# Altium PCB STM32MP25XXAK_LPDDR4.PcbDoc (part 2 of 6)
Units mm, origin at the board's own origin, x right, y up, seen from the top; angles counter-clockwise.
Board outline 120 x 79.6 mm, 4 copper layers (Top Layer, Signal Layer 1, Signal Layer 2, Bottom Layer), stack 1.614 mm thick; 190 components, 143 nets, 1208 pads, 757 vias.
Unrouted connection lines stored in the file: 3.
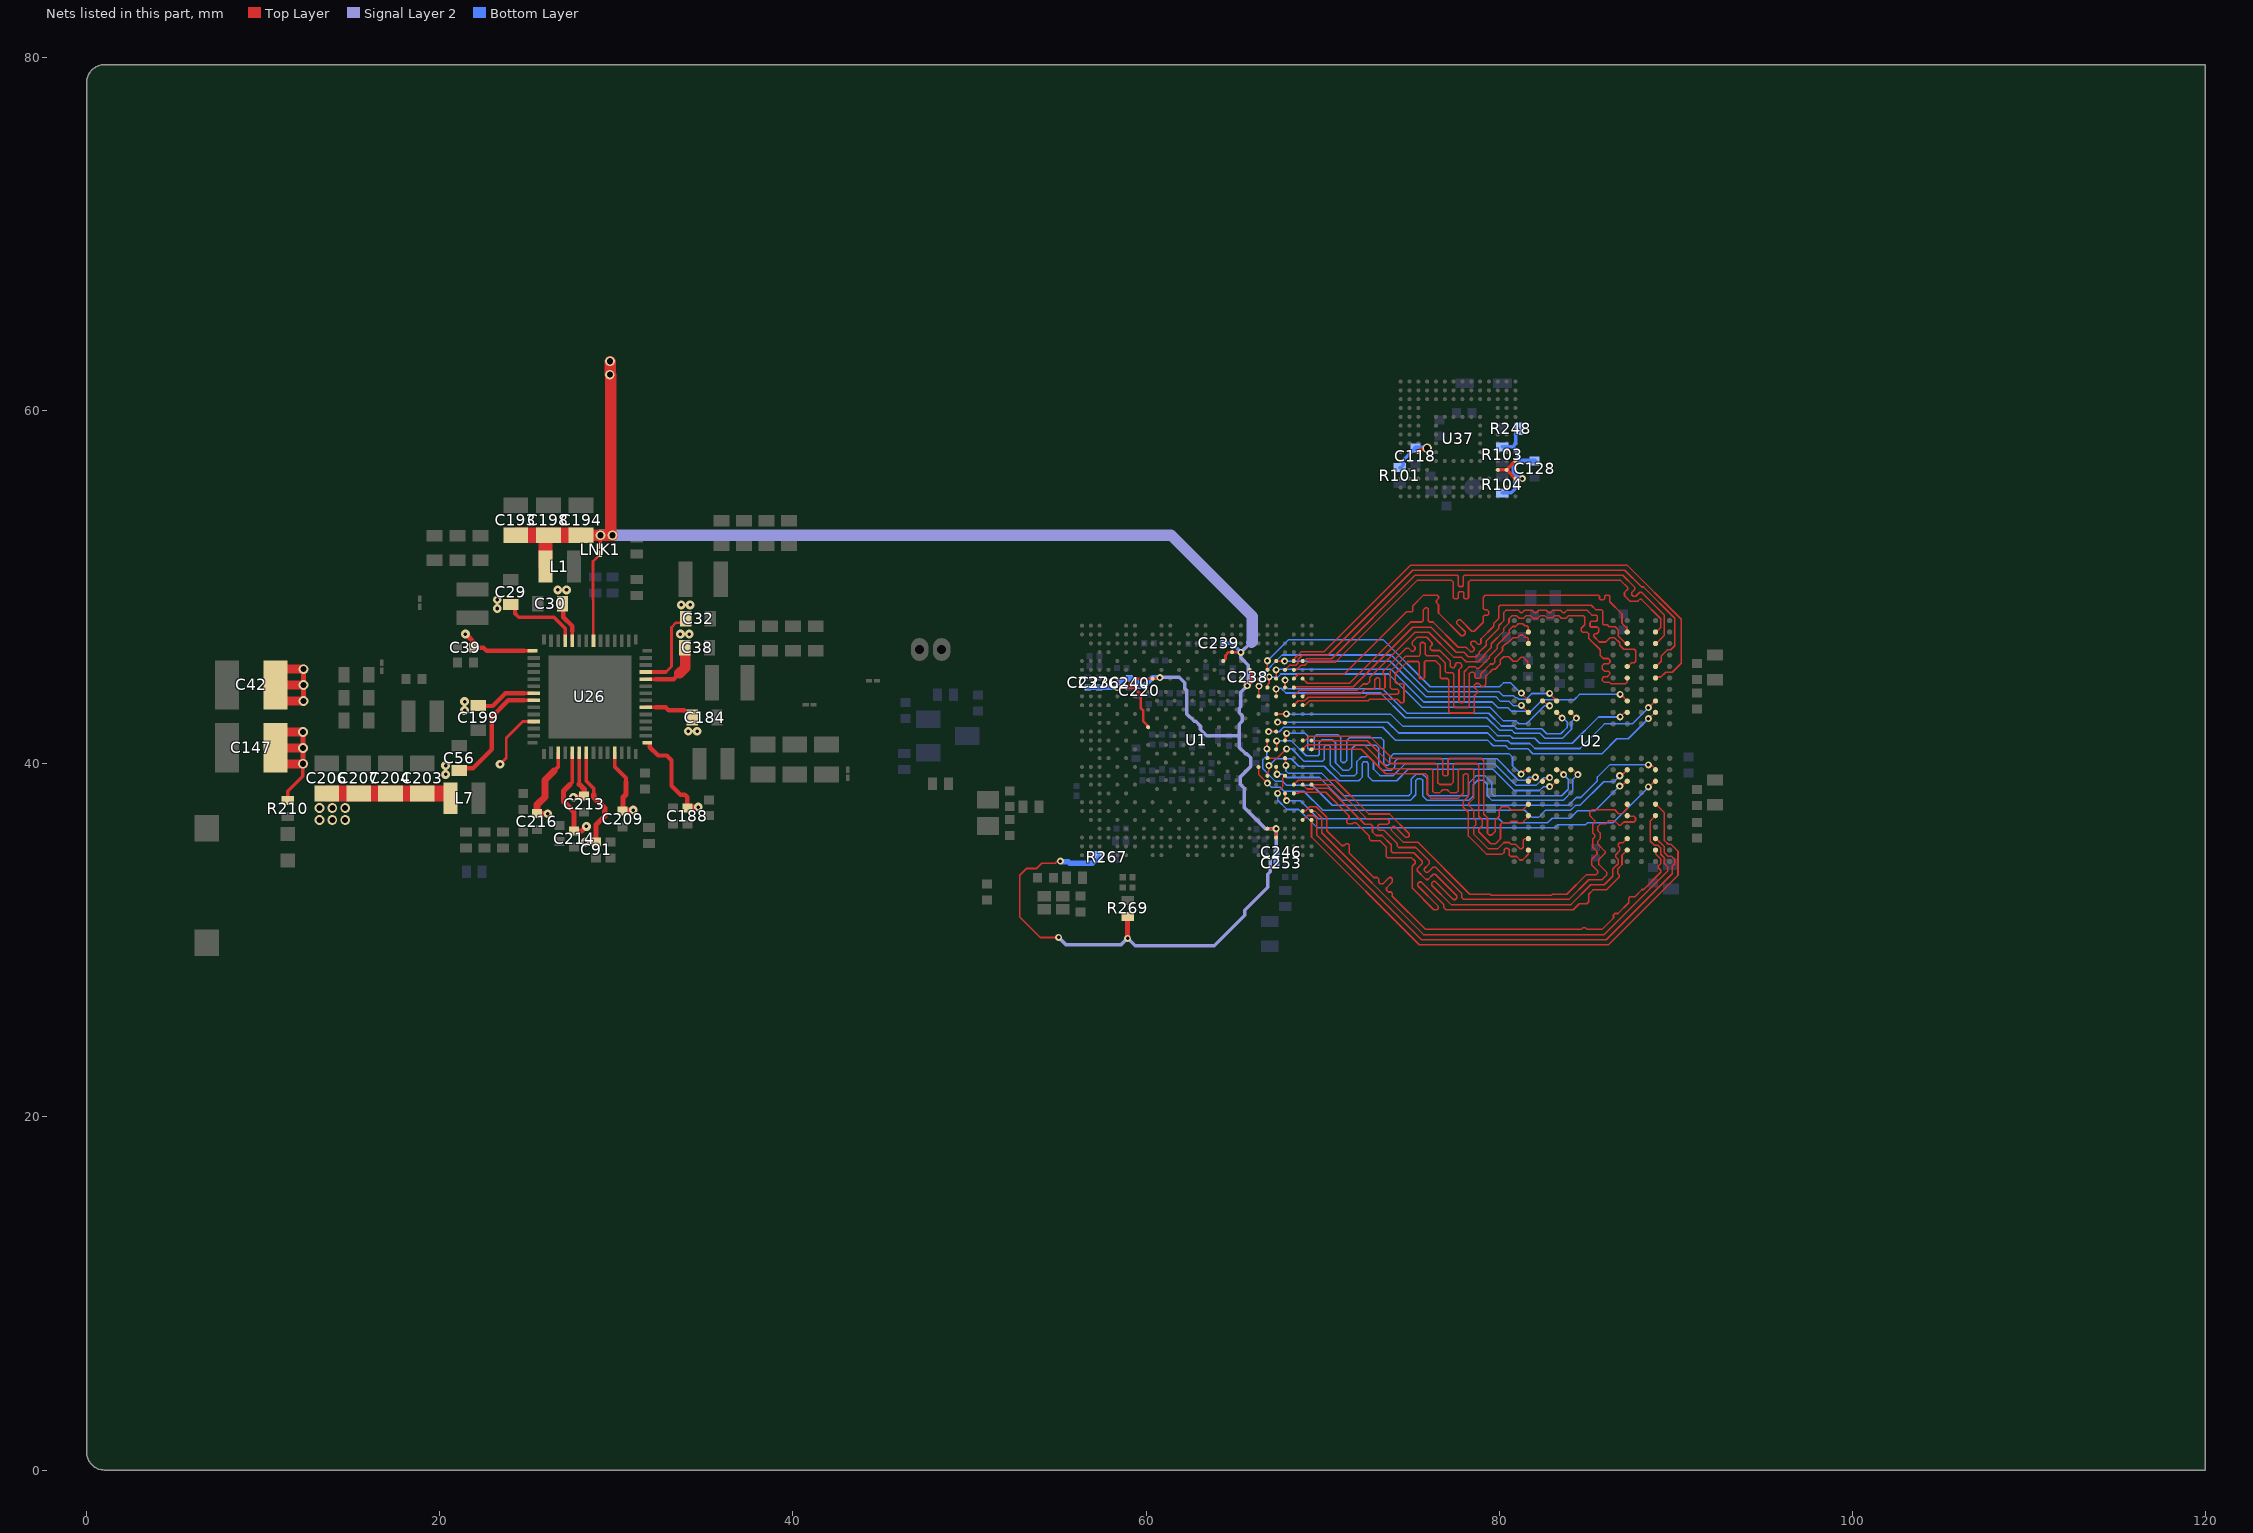
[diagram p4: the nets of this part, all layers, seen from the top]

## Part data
B2: library part MCD-03492, "Switch tactile, SPST-NO, 50mA, 12V, 6x3.8mm", Manufacturer="WURTH ELEKTRONIC", Manufacturer_Part_Number=434121025816, Package=6x3.8mm
C2 C3 C10 C11: library part MCD-01341, "Capacitor, MLCC, 10uF, 6V3, X5R, 20%, 0603, T=0,8mm", Alternate_Manufacturer=MURATA, Alternate_Manufacturer_Part_Number=GRM188R60J106ME84D, Manufacturer_Part_Number=GRM188R60J106ME47D, Package=0603
C4 C5 C6 C7 C8 C12 C13 C14 C15 C16 C17 C18 C19 C20 C21: library part MCD-00006, "Capacitor, MLCC, 100nF, 16V, X7R, +/-10%, 0402, T=0.5mm", Manufacturer=YAGEO, Manufacturer_Part_Number=CC0402KRX7R7BB104, Package=0402
C9 C118 C130: library part MCD-00006, "Capacitor, MLCC, 100nF, 16V, X7R, +/-10%, 0402, T=0.5mm", Alternate_Manufacturer=MURATA, Alternate_Manufacturer_Part_Number=GCM155R71C104KA55D, Manufacturer=YAGEO, Manufacturer_Part_Number=CC0402KRX7R7BB104, Package=0402
C22 C23 C24 C26 C27 C28 C34 C35 C36 C37 C41 C183 C200 C202: library part MCD-00100, "Capacitor, MLCC, 22uF, 6V3, X5R, +/-20%, 0603, T=0,8mm", Alternate_Manufacturer=N/A, Manufacturer=MURATA, Manufacturer_Part_Number=GRM188R60J226MEA0J, Package=0603
C29 C30 C32 C38 C56 C184 C199: library part MCD-00099, "Capacitor, MLCC, 10uF, 10V, X5R, +/-10%, 0603, T=0,8mm", Alternate_Manufacturer=N/A, Manufacturer=MURATA, Manufacturer_Part_Number=GRM188R61A106KE69D, Package=0603
C33: library part MCD-00011, "Capacitor, MLCC, 10nF, 16V, X7R, 10%, 0402, T=0.5mm", Manufacturer=YAGEO, Manufacturer_Part_Number=CC0402KRX7R7BB103, Package=C0402
C39 C43 C188 C213 C216: library part MCD-00095, "Capacitor, MLCC, 1uF, 25V, X5R, +/-10%, 0402, T=0.5mm", Manufacturer=MURATA, Manufacturer_Part_Number=GRM155R61E105KA12, Package=0402
C40: library part MCD-03140, "Capacitor, MLCC, 10uF, 6.3V, X5R, +/-20%, 0402, T=0.5mm", Manufacturer=MURATA, Manufacturer_Part_Number=GRM155R60J106ME05D, Package=0402
C42 C147: library part MCD-01796, "Capacitor, Tantalum, 100uF, 6V3, 40mR, +/-20%,  Type_B (3528 metric), T=1.9mm", Manufacturer=AVX, Manufacturer_Part_Number=TCJB107M006R0040, Package="3528 (metric)"
C44 C45 C46 C47 C48 C49 C50 C51 C52 C53 C54 C55 C57 C58 C59 C60 C62 C63 C64 C65 C66 C67 C68 C69 C70 C71 C72 C73 C74 C75 C76 C77 C82 C83: library part MCD-02377, "Capacitor, MLCC, 1uF, 6.3V, X5R, +/-20%, 0201, T=0,3mm", Manufacturer=MURATA, Manufacturer_Part_Number=GRM033R60J105MEA2, Package=0201
C61 C91 C189 C190 C208 C209 C214 C215 C217: library part MCD-01356, "Capacitor, MLCC, 4.7uF, 6V3, X5R, +/-20%, 0402, T=0.5mm", Manufacturer=MURATA, Manufacturer_Part_Number=GRM155R60J475ME47, Package=0402
C81 C86 C90 C92: library part MCD-00674, "Capacitor, MLCC, 6.8pF, 50V, NPO, +-0.25pF, 0402, T=0.5mm", Alternate_Manufacturer=N/A, Manufacturer=YAGEO, Manufacturer_Part_Number=CC0402CRNPO9BN6R8, Package=0402
C87: library part MCD-00006, "Capacitor,100nF,16V,X7R,10%,0402", Alternate_Manufacturer=MURATA, Alternate_Manufacturer_Part_Number=GCM155R71C104KA55D, Manufacturer=YAGEO, Manufacturer_Part_Number=CC0402KRX7R7BB104, Package=0402
C88: library part MCD-01823, "Capacitor, MLCC, 2.2uF, 6V3, X5R,+/-10%, 0402, T=0.5mm", Alternate_Manufacturer=N/A, Manufacturer=MURATA, Manufacturer_Part_Number=GRM155R60J225KE95D, Package=0402
C117 C128 C148: library part MCD-02606, "Capacitor, MLCC, 2.2uF, 6.3V, X5R, +/-10%, 0402, T=0.5mm", Manufacturer=YAGEO, Manufacturer_Part_Number=CC0402KRX5R5BB225, Package=0402
C151 C250 C252 C260: library part MCD-02377, "Capacitor, MLCC, 1uF, 6.3V, X5R, +/-20%, 0201, T=0,3mm", Alternate_Manufacturer=N/A, Manufacturer=MURATA, Manufacturer_Part_Number=GRM033R60J105MEA2, Package=0201
C185 C186 C187 C193 C194 C198 C203 C204 C206 C207: library part MCD-03139, "Capacitor, MLCC, 22uF, 10V, X5R, +/-20%, 0805, T=1,25mm", Manufacturer=MURATA, Manufacturer_Part_Number=GRM21BR61A226ME51L, Package=0805
C192 C195 C196 C197 C201 C205 C220 C234 C236 C237 C238 C239 C240 C244 C246 C248 C251 C253: library part MCD-01535, "Capacitor, MLCC,100nF, 10V, X7R, +/-10%, 0201, T=0.3mm", Alternate_Manufacturer=N/A, Manufacturer=MURATA, Manufacturer_Part_Number=GRM033R61A104KE15, Package=0201
C219: library part MCD-02198, "Capacitor, MLCC, 10nF, 50V, X7R, +/-10%, 0402, T=0.5mm", Manufacturer=YAGEO, Manufacturer_Part_Number=CC0402KRX7R9BB103, Package=0402
C225: library part MCD-01534, "Capacitor, MLCC, 4,7uF, 6V3, X5R, +/-20%, 0201, T=0.5mm", Alternate_Manufacturer=N/A, Manufacturer=MURATA, Manufacturer_Part_Number=GRM035R60J475ME15, Package=0201
C235: library part MCD-02235, "Capacitor, MLCC, 2.2uF, 10V, X5R,+/-10%, 0201, T=0.5mm", Manufacturer=MURATA, Manufacturer_Part_Number=GRM033R61A225KE47D, Package=0201
CN12: library part MCD-00655, "Header 2 circuits, 1.25mm Pitch ,  Vertical, with Friction Lock", Alternate_Manufacturer=N/A, Manufacturer=MOLEX, Manufacturer_Part_Number=53047-0210
D6: library part MCD-03280, "Diode, Schottky, Dual Common Cathode, 0V3, 300mA, 40V, SOT-23", Manufacturer=STMICROELECTRONICS, Manufacturer_Part_Number=BAT54CFILM, Package=SOT-23
D7: library part MCD-00034, Manufacturer=STMICROELECTRONICS, Manufacturer_HQ_COO=EU
L1 L6: library part MCD-03143, "Inductor, 2.2uH, +/-20%, Itemp= 1700mA, Isat= 2400mA, 0R140, 0806, T=1mm", Manufacturer=MURATA, Manufacturer_Part_Number=DFE201610E-2R2M{}P2, Package=0806
L2 L4: library part MCD-03142, "Inductor, 0.68uH, +/-20%, Itemp= 3900mA, Isat= 5400mA, 0R031, 1008, T=1.2mm", Manufacturer=MURATA, Manufacturer_Part_Number=DFE252012F-R68M{}P2, Package=1008
L3 L5 L7: library part MCD-03141, "Inductor, 0.68uH, +/-20%, Itemp= 3100mA, Isat= 4300mA, 0R043, 0806, T=1mm", Manufacturer=MURATA, Manufacturer_Part_Number=DFE201610E-R68M{}P2, Package=0806
LD11: library part MCD-00588, "LED Green, 0603 SMD, Forward Voltage Typ=2V, Max=2.5V", Alternate_Manufacturer="VISHAY SEMICONDUCTOR OPTO DIVISION", Alternate_Manufacturer_Part_Number=VLMTG1300-GS08, Manufacturer="OSRAM OPTO SEMICONDUCTORS", Manufacturer_Part_Number="LG Q396-PS-35", Package="LED 0603"
LNK1 LNK2 LNK4 LNK7 LNK8 LNK11: library part MCD-02777, "Track link on PCB 200um width for layout routing", Manufacturer=N/A
R1 R2: library part MCD-02253, "Resistor, 240R, 0201, +/-1%, 1/20W", Alternate_Manufacturer=N/A, Manufacturer=YAGEO, Manufacturer_Part_Number=RC0201FR-07240RL, Package=0201
R11: library part MCD-00056, "Resistor, 0R, 0603, +/-5%, 1/10W", Manufacturer=YAGEO, Manufacturer_Part_Number=RC0603JR-070RL, Package=0603
R27 R272: library part MCD-00053, "Resistor,10K,0402,1%,1/16W", Alternate_Manufacturer=N/A, Manufacturer=YAGEO, Manufacturer_Part_Number=RC0402FR-0710KL, Package=0402
R42: library part MCD-00053, "Resistor, 10K, 0402, +/-1%, 1/16W", Alternate_Manufacturer=N/A, Manufacturer=YAGEO, Manufacturer_Part_Number=RC0402FR-0710KL, Package=0402
R46 R57 R59 R60 R61 R64 R75 R81 R267 R269 R286: library part MCD-00052, "Resistor,0R,0402,5%,1/16W", Alternate_Manufacturer=N/A, Manufacturer=YAGEO, Manufacturer_Part_Number=RC0402JR-070RL, Package=0402
R66: library part MCD-00058, "Resistor, 20R, 0402, +/-1%, 1/16W", Alternate_Manufacturer=N/A, Manufacturer=YAGEO, Manufacturer_Part_Number=RC0402FR-0720RL, Package=0402
R67: library part MCD-00052, "Resistor, 0R, 0402, +/-5%, 1/16W", Manufacturer=YAGEO, Manufacturer_Part_Number=RC0402JR-070RL, Package=0402
R101 R103 R104 R248: library part MCD-00053, "Resistor,10K,0402,1%,1/16W", Manufacturer=YAGEO, Manufacturer_Part_Number=RC0402FR-0710KL, Package=0402
R210: library part MCD-00441, "Resistor,270R,0402,1%,1/16W", Manufacturer=YAGEO, Manufacturer_Part_Number=RC0402FR-07270RL, Package=0402
R260 R261: library part MCD-00068, "Resistor,1K5,0402,1%,1/16W", Manufacturer=YAGEO, Manufacturer_Part_Number=RC0402FR-071K5L, Package=0402
TP21: library part MCD-00074, "Test Point 1mm", Manufacturer=n/a
U1: library part MCD-03375, "MPU , 2xCortex-A35@1.5GHz, Cortex-M33@400MHz, TFBGA 14x14, pitch 0.5, 808 KB SRAM, With Crypto", Manufacturer=STMICROELECTRONICS, Package=TFBGA
U2: library part MCD-04160, "Memory, LPDDR4 SDRAM,1V8, 32Gbit, 2133MHz", Manufacturer=MICRON, Package=TFBGA-200
U26: library part MCD-03000, "STPMIC2", Manufacturer=STMICROELECTRONICS, Package=VQFN
U37: library part MCD-02799, "Memory, eMMC, 4GB, 15nm ,WFBGA , 153 pins", Manufacturer=KIOXIA, Manufacturer_Part_Number=THGBMTG5D1LBAIL, Package=WFBGA153
X1: library part MCD-01479, "Crystal, 32.768kHz, 6pF, +/-20ppm, 80K, 2.05x1.2mm", Manufacturer=NDK, Manufacturer_Part_Number=NX2012SA-32.768KHZ-EXS00A-MU00527, Package=2.05x1.2mm
X2: library part MCD-02344, "Crystal, 40MHz, 6pF, +/-20ppm, 80R, 1.6x1.2mm", Manufacturer=NDK, Manufacturer_Part_Number=NX1612SA-40MHZ-EXS00A-CS13836, Package=1.6x1.2mm

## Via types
v1: diameter 0.55, hole 0.35, Top Layer to Bottom Layer, 277 vias
v2: diameter 0.4, hole 0.2, Top Layer to Bottom Layer, tented both sides, 229 vias
v3: diameter 0.5, hole 0.2, Top Layer to Bottom Layer, 146 vias
v4: diameter 0.4, hole 0.2, Top Layer to Bottom Layer, 105 vias

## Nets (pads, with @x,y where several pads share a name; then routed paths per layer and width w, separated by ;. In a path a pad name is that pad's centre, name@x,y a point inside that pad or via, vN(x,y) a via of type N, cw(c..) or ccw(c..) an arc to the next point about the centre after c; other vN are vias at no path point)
1V8: C118.2 C128.2 C193.2 C194.2 C198.2 C220.2 C236.2 C237.2 C238.2 C239.2 C240.2 C246.2 C253.2 L1.2 LNK1.2 R101.2 R103.2 R104.2 R248.2 R267.2 R269.1 U1.1E1 U1.AD22 U1.AE23 U1.D18 U1.E17 U1.F20 U1.G5 U1.G7 U1.G9 U1.G19 U1.H6 U37.C6 U37.M4 U37.N4 U37.P3 U37.P5 | length 137.4
  Top Layer w0.1: v2(55.049,30.165) 54.012,30.165 52.854,31.323 52.854,33.688 53.244,34.078 53.813,34.078 54.103,34.368 54.86,34.368 54.967,34.474 55.127,34.474 v2(55.146,34.494)
  Top Layer w0.15: U1.G5@58.375,44.825 v2(58.375,44.325) U1.H6@58.875,44.325 ; U1.1E1@60.125,42.075 60.125,42.097 60.085,42.137 60.085,42.17 59.835,42.42 59.835,43.035 59.702,43.168 59.702,43.926 59.304,44.325 U1.H6@58.875,44.325 ; v2@60.792,44.887 v2(60.79,44.885) 60.73,44.825 U1.G9@60.375,44.825 U1.G7@59.375,44.825 U1.H6@58.875,44.325 ; U1.E17@64.375,45.825 64.375,45.828 64.5,45.953 64.5,46.139 64.683,46.322 U1.D18@64.872,46.322 ; U1.D18@64.853,46.325 U1.D18@64.875,46.325 65.372,46.325 v2(65.378,46.319) ; U1.G19@65.378,44.822 65.735,44.465 v2(65.735,44.426) 65.735,44.412 65.973,44.651 65.973,45.205 65.875,45.303 U1.F20@65.875,45.325 ; U1.AD22@66.875,36.325 v2(67.375,36.325) U1.AE23@67.375,35.825 ; U37.P3@80.925,56.155 v2(81.325,56.155)
  Top Layer w0.2: LNK1.2@29.1,52.348 v1(29.1,52.95) ; U37.C6@75.425,57.655 75.602,57.832 75.877,57.832 v1(75.925,57.88) ; U37.M4@79.925,56.655 U37.N4@80.425,56.655 ; U37.P3@80.925,56.155 U37.N4@80.425,56.655 ; U37.P5@80.925,57.155 U37.N4@80.425,56.655
  Top Layer w0.3: R269.1@58.956,31.358 58.956,30.117 v2(58.962,30.112)
  Top Layer w0.64: C194.2@28,52.95 v1(29.1,52.95) v1(29.78,52.95) 29.674,53.056 v1@29.674,62.004 ; v1@29.66,62.075 v1@29.66,62.782
  Top Layer w0.8: L1.2@25.995,51.175 25.995,52.9 26.045,52.95 C198.2@26.15,52.95
  Top Layer w0.9: C193.2@24.3,52.95 C198.2@26.045,52.95 ; C198.2@26.15,52.95 C194.2@28,52.95
  Signal Layer 2 w0.2: v2(55.049,30.165) 55.449,29.766 58.598,29.766 v2@58.944,30.112 ; v2(58.962,30.112) 59.386,29.688 63.861,29.688 65.603,31.43 65.603,31.711 66.9,33.008 66.9,33.754 67.041,33.895 67.041,34.559 67.375,34.893 v2(67.375,36.325) ; v2(60.79,44.885) 60.811,44.906 61.89,44.906 62.2,44.596 62.2,44.264 62.32,44.144 62.32,42.814 62.725,42.409 62.81,42.409 63.077,42.143 ; 63.075,42.156 63.077,42.155 63.077,42.143 ; 65.285,41.575 65.285,40.928 65.64,40.572 65.694,40.572 65.93,40.336 65.93,39.851 65.349,39.271 65.349,38.835 65.569,38.615 65.569,37.527 65.566,37.525 66.77,36.322 v2@67.372,36.322 ; v2@65.674,44.353 65.773,44.452 65.773,44.591 65.794,44.612 65.794,45.583 65.378,45.999 v2(65.378,46.319) 65.927,46.868 65.981,46.868 ; v2@65.734,44.411 65.375,44.053 65.375,43.231 65.284,43.14 65.284,42.894 65.44,42.738 65.44,42.406 65.285,42.251 65.285,41.593 63.445,41.593 63.077,41.961 63.077,42.143
  Signal Layer 2 w0.64: v1@29.1,52.955 v1@29.78,52.955 ; v1(29.78,52.95) 61.405,52.95 ; 61.411,52.956 66.023,48.344 66.023,46.91 65.981,46.868
  Bottom Layer w0.15: v2(67.375,36.325) 67.375,34.827 67.391,34.811
  Bottom Layer w0.2: C239.2@64.4,46.837 64.86,46.837 v2(65.378,46.319) ; v2@65.735,44.411 65.958,44.635 65.958,44.819 C238.2@66.033,44.894 ; R101.2@74.375,56.775 74.425,56.775 74.58,56.93 74.58,57.2 75.08,57.7 75.08,57.725 75.235,57.88 C118.2@75.26,57.88 ; R103.2@80.171,57.961 80.769,57.961 ; R104.2@80.175,55.355 80.69,55.355 80.885,55.55 80.885,55.998 81.061,56.174 ; 81.075,57.136 81.075,57.655 80.769,57.961 ; R248.2@81.107,58.98 80.952,58.825 80.952,58.144 80.769,57.961
  Bottom Layer w0.25: C253.2@67.391,34.385 67.391,34.811 C246.2@67.391,34.986
  Bottom Layer w0.3: v2(55.146,34.494) 55.165,34.474 55.236,34.474 55.259,34.452 55.612,34.452 55.689,34.375 56.975,34.375 57.123,34.523 57.218,34.523 57.323,34.628 R267.2@57.323,34.723 ; C237.2@56.696,44.325 C236.2@57.35,44.325 v2@58.386,44.325 ; v2(58.375,44.325) 58.394,44.344 58.394,44.53 58.689,44.825 59.025,44.825 C240.2@59.025,44.85 ; C240.2@58.984,44.85 59.125,44.85 59.15,44.825 59.19,44.825 59.3,44.715 59.399,44.715 59.54,44.574 59.54,44.475 C220.2@59.609,44.406 59.634,44.431 59.911,44.431 60.372,44.892 60.783,44.892 v2(60.79,44.885) ; C118.2@75.26,57.88 v1(75.925,57.88) ; v2(81.325,56.155) 81.306,56.174 81.061,56.174 80.867,56.368 80.867,56.928 81.075,57.136 81.306,57.136 81.325,57.155 C128.2@82.015,57.155
  other v1: 29.631,62.047 29.642,62.8
1V8_FB: LNK1.1 U26.35 | length 5.1
  Top Layer w0.15: U26.35@28.7,46.97 28.7,49.311 28.675,49.336 28.675,51.473 LNK1.1@29.1,51.898
3V3: C203.2 C204.2 C206.2 C207.2 C216.2 L7.2 U26.3 U26.53 | length 15.3
  Top Layer w0.15: v3(23.41,39.977) 23.762,40.329 23.762,41.465 24.697,42.4 U26.53@25.33,42.4 ; U26.53@25.12,42.369 25.419,42.369 U26.53@25.45,42.4
  Top Layer w0.21: 26.473,39.598 26.7,39.825 U26.3@26.7,40.63
  Top Layer w0.3: C216.2@25.475,37.175 C216.2@25.5,37.175 v3@26.085,37.175
  Top Layer w0.4: C216.2@25.5,37.175 25.514,37.189 25.514,37.685 25.96,38.131 25.96,39.085 26.473,39.598
  Top Layer w0.9: C206.2@13.587,38.323 C203.2@19,38.323 20.362,38.323 L7.2@20.387,38.298
  other v1: 13.187,36.823 13.912,36.823 14.637,36.823 13.187,37.498 13.912,37.498 14.637,37.498
  other v3: 26.11,37.175
5V_HDMI: C91.1 U26.7 | length 6.1
  Top Layer w0.21: U26.7@28.3,40.63 28.3,39.025 28.715,38.61 28.715,38.253
  Top Layer w0.3: v3(28.24,35.58) C91.1@28.85,35.58 ; 28.715,38.253 28.715,38.118 29.335,37.498 29.335,37.035 28.85,36.55 C91.1@28.85,35.73
5V_STLK: C29.2 C30.2 C32.2 C38.2 C39.2 C42.1 C56.2 C147.1 C184.2 C188.2 C199.2 C209.2 C213.2 R210.1 U26.6 U26.11 U26.15 U26.20 U26.24 U26.25 U26.38 U26.39 U26.43 U26.49 U26.50 | length 61
  Top Layer w0.15: 32.8,45.2 33.125,45.525 33.125,47.731 33.388,47.994 33.819,47.994 C32.2@33.925,48.1
  Top Layer w0.2: R210.1@11.386,37.915 11.386,38.449 12.244,39.307 v1@12.244,39.994
  Top Layer w0.21: C29.2@24.025,49.05 24.262,48.813 24.262,48.513 24.475,48.3 26.464,48.3 27.1,47.664 U26.39@27.1,46.97 ; 24.775,43.6 U26.50@25.33,43.6 ; 24.775,44 U26.49@25.33,44 ; 24.775,46.4 U26.43@25.33,46.4 ; U26.38@27.5,46.97 27.5,47.525 ; 27.9,38.85 U26.6@27.9,40.63 ; U26.11@29.9,40.63 29.9,39.843 30.54,39.203 30.54,38.975 ; U26.15@31.67,41.2 U26.15@31.745,41.2 U26.15@31.785,41.2 ; U26.20@31.67,43.2 32.225,43.2 ; U26.24@31.67,44.8 32.207,44.8 ; U26.25@31.67,45.2 32.8,45.2
  Top Layer w0.25: C56.2@21.1,39.75 21.875,39.75 22.95,40.825 22.95,42.669 23.881,43.6 24.775,43.6 ; 21.695,47.125 21.699,47.125 21.845,46.979 21.845,46.685 C39.2@21.955,46.575 ; C39.2@22.005,46.575 22.475,46.575 22.65,46.4 24.775,46.4 ; C199.2@22.175,43.275 22.991,43.275 23.716,44 24.775,44 ; C30.2@26.925,49.075 26.994,49.006 26.994,48.308 27.5,47.802 27.5,47.525 ; 31.895,41.095 31.895,40.947 32.371,40.472 32.853,40.472 33.125,40.2 33.125,38.759 33.634,38.25 33.879,38.25 34.025,38.104 C188.2@34.025,37.55 ; 32.207,44.8 33.25,44.8 33.575,45.125 ; 32.225,43.2 32.788,43.2 32.963,43.025 33.847,43.025 33.972,42.9 34.05,42.9 34.247,42.703 C184.2@34.247,42.625
  Top Layer w0.3: v1@12.25,40 12.25,40.902 12.25,40.906 v1@12.25,41.8 ; v1@12.275,43.563 12.275,44.463 v1@12.275,45.363 ; v3@21.444,47.376 21.695,47.125 ; v3(27.565,38.11) 28.175,38.11 28.174,38.111 28.174,38.576 27.9,38.85 ; C209.2@30.35,37.38 C209.2@30.375,37.38 ; 30.54,38.975 30.54,38.269 30.375,38.104 C209.2@30.375,37.38 ; v3(30.96,37.38) C209.2@30.375,37.38 ; C188.2@34.025,37.55 v3(34.635,37.55)
  Top Layer w0.5: C147.1@10.686,39.994 12.244,39.994 v1@12.269,39.994 ; C147.1@10.686,40.906 12.25,40.906 v1@12.269,40.906 ; C147.1@10.686,41.806 v1@12.269,41.806 ; C42.1@10.686,43.557 v1@12.269,43.557 ; C42.1@10.686,44.468 v1@12.269,44.468 ; C42.1@10.686,45.368 v1@12.269,45.368
  Top Layer w0.6: 33.575,45.125 33.9,45.45 C38.2@33.9,46.175
  other v1: 12.251,40.002 12.251,40.902 12.251,41.802 12.276,43.565 12.276,44.465 12.276,45.365
  other v3: 20.325,39.4 20.325,39.9 34.075,41.85 34.575,41.85 21.4,43.025 21.4,43.525 21.45,47.348 33.625,47.35 34.125,47.35 23.25,48.8 33.675,49 34.175,49 23.25,49.3 26.675,49.85 27.175,49.85
5V_VCONN: C214.1 U26.5 | length 5.7
  Top Layer w0.21: 27.378,38.827 27.5,38.95 U26.5@27.5,40.63
  Top Layer w0.3: 27.378,38.827 27.01,38.46 27.01,37.865 27.6,37.275 C214.1@27.6,36.2 28.04,36.2 v3(28.3,36.46)
DDR_CA0_A: U1.V24 U2.H2 | length 24.6
  Top Layer w0.09: v2@67.471,38.421 67.471,38.432 67.735,38.695 67.735,39.185 U1.V24@67.875,39.325 ; v4(88.46,38.69) 88.497,38.69 88.814,39.007 U2.H2@88.873,39.007
  Bottom Layer w0.09: v2@67.463,38.318 67.463,37.935 67.983,37.415 68.659,37.415 69.683,36.39 83.176,36.39 83.326,36.54 84.88,36.54 85.007,36.667 86.447,36.667 v4@88.461,38.681
  other v2: 67.46,38.325
DDR_CA0_B: U1.M24 U2.R2 | length 23.5
  Top Layer w0.09: v2@67.46,42.35 67.484,42.326 U1.M24@67.875,42.325 ; v4@88.472,43.19 88.826,43.544 U2.R2@88.859,43.544
  Bottom Layer w0.09: v2(67.46,42.365) 73.699,42.365 ; 73.7,42.36 74.314,41.746 79.358,41.746 79.791,41.313 80.496,41.313 80.654,41.155 81.746,41.155 82.031,40.87 84.581,40.87 85.973,42.262 87.538,42.262 v4@88.461,43.185
  other v4: 88.46,43.19
DDR_CA1_A: U1.P22 U2.J2 | length 25.9
  Top Layer w0.09: v2@66.875,40.9 U1.P22@66.875,41.325 ; v4(88.46,39.94) 88.518,39.881 88.689,39.881 88.86,39.71 U2.J2@88.86,39.665
  Bottom Layer w0.09: v2@66.851,40.845 66.851,40.48 66.622,40.251 66.622,40.045 66.62,40.043 66.62,39.757 66.622,39.755 66.622,39.721 67.339,39.005 67.74,39.005 67.954,38.791 69.421,38.791 70.552,37.66 83.935,37.66 84.371,38.096 84.618,38.096 85.572,39.05 85.572,39.255 86.257,39.94 v4(88.46,39.94)
  other v2: 66.85,40.85
DDR_CA1_B: U1.N23 U2.P2 | length 24
  Top Layer w0.09: v2@66.946,41.838 67.362,41.838 U1.N23@67.375,41.825 ; v4(88.46,42.565) 88.483,42.565 88.833,42.915 U2.P2@88.86,42.915
  Bottom Layer w0.09: v2(66.95,41.825) 67.542,41.825 67.792,42.075 73.404,42.075 74.153,41.326 79.367,41.326 79.669,41.023 80.374,41.023 80.533,40.865 81.624,40.865 81.909,40.58 85.826,40.58 86.671,41.425 87.315,41.425 88.45,42.56 v4@88.461,42.56
DDR_CA2_A: U1.V22 U2.H9 | length 20.3
  Top Layer w0.09: U1.V22@66.877,39.334 66.877,39.497 66.947,39.567 66.947,39.847 v2@66.95,39.85 ; v4@82.859,38.719 82.913,38.774 83.019,38.774 U2.H9@83.26,39.015
  Bottom Layer w0.09: v2@66.966,39.895 67.358,40.287 68.23,40.287 68.647,39.869 70.104,39.869 70.926,39.046 72.053,39.046 72.239,39.232 72.239,40.017 72.339,40.117 72.501,40.117 72.595,40.024 72.595,39.281 72.83,39.046 74.2,39.046 74.859,39.705 79.637,39.705 80.852,38.49 82.293,38.49 82.511,38.708 v4@82.86,38.708
  other v2: 66.965,39.9
  other v4: 82.86,38.715
DDR_CA2_B: U1.J21 U2.R9 | length 19.8
  Top Layer w0.09: U1.J21@66.375,43.825 66.387,43.837 v2@66.387,44.388 ; v4(82.86,43.99) 82.86,43.977 83.26,43.577 U2.R9@83.26,43.565
  Bottom Layer w0.09: v2(66.4,44.4) 66.4,44.478 66.494,44.572 66.494,44.951 67.71,46.166 73.892,46.166 75.974,44.084 79.99,44.084 80.217,43.857 80.817,43.857 80.918,43.756 81.021,43.756 81.117,43.66 81.519,43.66 81.846,43.987 v4@82.858,43.987
DDR_CA3_A: U1.T22 U2.H10 | length 21.6
  Top Layer w0.09: U1.T22@66.875,40.325 67.433,40.325 v2(67.961,40.853) ; U2.H10@82.467,39.008 82.625,39.166 82.801,39.166 v4(82.86,39.225)
  Bottom Layer w0.09: v2@67.964,40.849 68.253,40.849 68.943,40.159 70.015,40.159 70.104,40.248 70.104,40.975 70.195,41.066 70.356,41.066 70.443,40.978 70.443,39.939 71.046,39.336 71.816,39.336 71.949,39.469 71.949,40.137 72.219,40.407 72.621,40.407 72.885,40.144 72.885,39.706 73.255,39.336 74.013,39.336 74.671,39.995 79.757,39.995 80.972,38.78 82.094,38.78 82.534,39.22 v4@82.861,39.22
DDR_CA3_B: U1.H22 U2.R10 | length 18.7
  Top Layer w0.09: U1.H22@66.875,44.325 66.9,44.35 66.9,44.496 66.975,44.571 66.975,44.918 v2(66.971,44.921) ; U2.R10@82.46,43.565 82.514,43.565 82.789,43.29 v4(82.86,43.29)
  Bottom Layer w0.09: v2@66.972,44.916 67.471,44.916 67.646,45.091 73.736,45.091 75.628,43.2 79.488,43.2 80.255,42.433 80.96,42.433 81.118,42.275 81.559,42.275 82.569,43.285 v4@82.861,43.285
DDR_CA4_A: U1.R23 U2.H11 | length 21.6
  Top Layer w0.09: U1.R23@67.375,40.825 67.4,40.85 v2(67.4,41.3) ; U2.H11@81.66,39.015 81.714,39.015 81.882,39.183 82.003,39.183 v4(82.06,39.24)
  Bottom Layer w0.09: v2(67.4,41.3) 68.236,41.3 69.072,40.465 69.736,40.465 69.814,40.543 69.814,41.209 69.962,41.356 70.569,41.356 70.733,41.192 70.733,40.059 71.166,39.626 71.466,39.626 71.659,39.819 71.659,40.858 71.849,41.048 73.031,41.048 73.175,40.904 73.175,39.826 73.375,39.626 73.892,39.626 74.093,39.826 74.093,40.136 74.241,40.285 79.877,40.285 81.092,39.07 81.517,39.07 81.686,39.239 v4@82.057,39.239
DDR_CA4_B: U1.F22 U2.R11 | length 17.4
  Top Layer w0.09: U1.F22@66.875,45.325 v2(66.875,45.841) ; v4@81.26,43.99 81.66,43.59 U2.R11@81.66,43.565
  Bottom Layer w0.09: v2@66.876,45.836 68.06,47.02 73.448,47.02 76.094,44.374 80.027,44.374 ; 80.044,44.379 80.249,44.584 80.665,44.584 v4@81.259,43.99
  other v4: 81.26,44.005
DDR_CA5_A: U1.P24 U2.J11 | length 21.1
  Top Layer w0.09: U1.P24@67.875,41.325 67.902,41.352 67.902,41.702 v2@67.95,41.75 ; v4@81.235,39.415 81.461,39.641 81.636,39.641 U2.J11@81.66,39.665
  Bottom Layer w0.09: v2@67.971,41.725 69.016,41.725 69.155,41.586 69.155,40.888 69.257,40.786 69.444,40.786 69.524,40.867 69.524,41.508 69.662,41.646 70.873,41.646 71.023,41.496 71.023,40.18 71.125,40.078 71.257,40.078 71.369,40.19 71.369,41.327 71.513,41.471 73.311,41.471 73.465,41.317 73.465,40.008 73.556,39.916 73.712,39.916 73.803,40.007 73.803,40.351 74.032,40.58 80.558,40.58 80.76,40.378 80.76,40.364 80.761,40.363 80.761,39.9 v4@81.251,39.41
  other v2: 67.97,41.73
  other v4: 81.25,39.415
DDR_CA5_B: U1.E23 U2.P11 | length 15.5
  Top Layer w0.09: U1.E23@67.375,45.825 67.377,45.823 67.852,45.823 v2(67.855,45.82) ; v4@81.268,43.3 81.652,42.915 U2.P11@81.66,42.915
  Bottom Layer w0.09: v2@67.856,45.815 73.833,45.815 75.854,43.794 79.829,43.794 80.085,43.538 80.573,43.538 80.822,43.289 81.24,43.289 v4@81.261,43.31
  other v4: 81.26,43.315
DDR_CKE0_A: U1.U21 U2.J4 | length 23.3
  Top Layer w0.09: U1.U21@66.376,39.833 66.376,39.409 v2(66.875,38.91) ; v4@86.979,39.384 U2.J4@87.26,39.665
  Bottom Layer w0.09: v2@66.876,38.905 67.111,38.67 67.603,38.67 67.818,38.455 68.939,38.455 70.024,37.37 81.458,37.37 81.863,36.965 82.229,36.965 82.629,37.365 84.05,37.365 84.329,37.644 84.576,37.644 85.922,38.99 86.515,38.99 v4@86.836,39.311
  other v4: 86.835,39.325
DDR_CKE0_B: U1.L23 U2.P4 | length 21.3
  Top Layer w0.09: U1.L23@67.375,42.825 67.816,42.826 67.88,42.889 v2@67.965,42.889 ; v4(86.86,42.665) 87.079,42.884 87.229,42.884 U2.P4@87.26,42.915
  Bottom Layer w0.09: v2@67.951,42.82 73.855,42.82 74.555,42.12 79.395,42.12 79.911,41.603 80.616,41.603 80.774,41.445 82.02,41.445 82.305,41.16 84.141,41.16 85.634,42.654 v4@86.855,42.654
  other v2: 67.95,42.825
DDR_CLK_A_N: U1.T24 U2.J9 | length 22.6
  Top Layer w0.09: U1.T24@67.876,40.333 67.901,40.308 67.901,39.933 v2@67.926,39.908 ; U2.J9@83.26,39.665 83.3,39.625 83.428,39.625 v4@83.659,39.394
  Bottom Layer w0.09: v2@67.929,39.902 67.929,39.595 68.048,39.476 69.936,39.476 71.211,38.2 74.886,38.2 75.034,38.348 75.034,39.159 75.29,39.415 75.683,39.415 75.925,39.172 75.925,38.286 76.011,38.2 78.213,38.2 78.291,38.277 78.291,38.915 78.692,39.316 79.204,39.316 79.578,38.941 79.578,38.301 79.68,38.2 83.553,38.2 83.915,38.561 83.915,39.135 v4(83.66,39.39)
  other v2: 67.925,39.91
DDR_CLK_A_P: U1.U23 U2.J8 | length 23.2
  Top Layer w0.09: U1.U23@67.375,39.825 67.375,39.46 v2(67.425,39.41) ; U2.J8@84.06,39.665 84.1,39.625 84.217,39.625 84.448,39.394 v4@84.459,39.394
  Bottom Layer w0.09: v2@67.427,39.404 67.766,39.404 67.945,39.226 69.832,39.226 71.108,37.95 74.989,37.95 75.284,38.245 75.284,39.055 75.393,39.165 75.579,39.165 75.675,39.069 75.675,38.182 75.908,37.95 78.317,37.95 78.541,38.174 78.541,38.811 78.795,39.066 79.1,39.066 79.328,38.838 79.328,38.198 79.576,37.95 83.657,37.95 84.165,38.458 84.165,39.096 v4(84.46,39.39)
DDR_CLK_B_N: U1.H24 U2.P9 | length 19.1
  Top Layer w0.09: U1.H24@67.875,44.325 v2(67.875,44.74) ; U2.P9@83.26,42.915 83.574,42.601 v4(83.574,42.59)
  Bottom Layer w0.09: v2(67.875,44.74) 67.851,44.716 67.851,44.441 68.027,44.265 73.389,44.265 74.785,42.869 79.409,42.869 80.135,42.143 80.839,42.143 80.998,41.985 82.422,41.985 82.707,41.7 83.49,41.7 83.85,42.06 83.85,42.383 83.649,42.584 v4@83.575,42.584
DDR_CLK_B_P: U1.J23 U2.P8 | length 19.8
  Top Layer w0.09: U1.J23@67.375,43.825 v2(67.375,44.24) ; U2.P8@84.06,42.915 84.06,42.909 v4@84.374,42.595
  Bottom Layer w0.09: v2@67.381,44.24 67.422,44.281 67.658,44.281 67.924,44.015 73.285,44.015 74.681,42.619 79.305,42.619 80.031,41.893 80.736,41.893 80.894,41.735 82.319,41.735 82.604,41.45 83.593,41.45 84.1,41.957 84.1,42.383 84.306,42.59 v4(84.374,42.59)
DDR_CS0_A: U1.Y24 U2.H4 | length 21.2
  Top Layer w0.09: U1.Y24@67.876,38.333 67.891,38.319 67.891,37.977 v2@67.967,37.901 ; v4(86.835,38.74) 86.893,38.799 87.002,38.799 87.217,39.015 U2.H4@87.26,39.015
  Bottom Layer w0.09: v2@67.971,37.915 68.747,37.915 69.769,36.893 79.992,36.893 80.209,36.675 82.756,36.675 83.005,36.924 84.02,36.924 84.45,37.354 85.449,37.354 v4(86.835,38.74)
  other v2: 67.97,37.92
DDR_CS0_B: U1.G23 U2.R4 | length 22
  Top Layer w0.09: U1.G23@67.375,44.825 v2(67.375,45.325) ; v4(86.86,43.94) 86.885,43.94 U2.R4@87.26,43.565
  Bottom Layer w0.09: v2@67.374,45.321 67.377,45.321 67.426,45.37 73.868,45.37 75.734,43.504 79.608,43.504 79.934,43.179 80.507,43.179 80.716,42.969 81.116,42.969 ; v4@86.861,43.935 84.557,43.935 84.257,43.635 82.461,43.635 81.791,42.965 81.786,42.97 81.117,42.97 ; 81.116,42.969 81.117,42.97
DDR_DQ0_A: U1.AB26 U2.B2 | length 28.6
  Top Layer w0.09: U1.AB26@68.875,37.325 68.901,37.351 69.047,37.351 69.271,37.575 69.643,37.575 70.245,36.973 70.245,36.216 71.087,35.374 71.222,35.374 71.329,35.481 71.433,35.481 71.516,35.398 71.516,34.945 72.9,33.561 73.102,33.561 73.182,33.482 73.182,33.279 73.261,33.2 73.413,33.2 73.775,33.561 73.886,33.561 73.956,33.492 73.956,33.304 73.623,32.971 73.623,32.838 73.718,32.743 73.877,32.743 73.956,32.664 73.956,32.505 75.841,30.62 84.663,30.62 84.748,30.705 84.917,30.705 85.001,30.62 85.834,30.62 86.48,31.266 86.48,31.447 86.554,31.521 86.735,31.521 87.343,32.129 87.343,32.392 87.415,32.464 87.678,32.464 88.095,32.881 88.187,32.881 89.159,33.853 89.159,33.975 89.016,34.117 89.016,34.218 89.159,34.361 89.159,34.609 88.878,34.89 88.878,35.075 U2.B2@88.859,35.094
DDR_DQ0_B: U1.F25 U2.AA2 | length 27.9
  Top Layer w0.09: U1.F25@68.375,45.325 68.389,45.339 68.535,45.339 68.771,45.575 68.979,45.575 68.983,45.579 68.992,45.579 69.182,45.769 70.734,45.769 75.355,50.39 77.311,50.39 77.399,50.301 77.399,49.414 77.47,49.344 77.625,49.344 77.696,49.415 77.696,49.699 77.751,49.754 77.943,49.754 77.996,49.701 77.996,49.416 78.069,49.344 78.198,49.344 78.269,49.414 78.269,50.298 78.361,50.39 86.882,50.39 87.285,49.987 87.285,49.888 87.106,49.71 87.106,49.524 87.419,49.21 87.854,49.21 87.957,49.313 88.065,49.313 89.154,48.224 89.154,47.723 88.875,47.444 U2.AA2@88.859,47.444
DDR_DQ1_A: U1.AC26 U2.C2 | length 28.7
  Top Layer w0.09: U1.AC26@68.877,36.829 68.897,36.829 69.143,37.075 69.479,37.075 69.665,36.889 69.665,35.976 75.601,30.04 86.074,30.04 89.813,33.779 89.813,34.215 89.945,34.347 89.945,34.585 89.761,34.769 89.567,34.769 89.364,34.972 89.364,35.306 88.905,35.765 U2.C2@88.86,35.765
DDR_DQ1_B: U1.E26 U2.Y2 | length 27.1
  Top Layer w0.09: U1.E26@68.877,45.829 68.9,45.852 68.996,45.852 69.103,45.959 70.514,45.959 75.235,50.68 77.637,50.68 77.689,50.627 77.689,50.097 77.742,50.044 77.926,50.044 77.979,50.097 77.979,50.614 78.045,50.68 87.002,50.68 87.695,49.987 87.695,49.889 87.518,49.712 87.518,49.577 87.596,49.5 87.734,49.5 87.96,49.726 88.062,49.726 89.364,48.424 89.364,47.29 88.868,46.794 U2.Y2@88.859,46.794
DDR_DQ2_A: U1.AB27 U2.E2 | length 28.9
  Top Layer w0.09: U1.AB27@69.375,37.325 69.571,37.325 69.955,36.941 69.955,36.096 75.721,30.33 85.954,30.33 89.564,33.94 89.564,34.158 89.349,34.373 89.349,34.687 89.154,34.882 89.154,35.237 88.991,35.4 88.786,35.4 88.564,35.622 88.564,36.769 U2.E2@88.86,37.065
DDR_DQ2_B: U1.F24 U2.V2 | length 29
  Top Layer w0.09: U1.F24@67.875,45.325 68.125,45.575 68.479,45.575 68.625,45.721 68.625,45.929 68.845,46.149 70.294,46.149 75.115,50.97 87.122,50.97 88.076,50.016 88.182,50.016 89.945,48.253 89.945,46.697 89.717,46.469 89.542,46.469 89.187,46.114 89.187,45.804 88.877,45.494 U2.V2@88.859,45.494
DDR_DQ3_A: U1.AC27 U2.F2 | length 30.5
  Top Layer w0.09: U1.AC27@69.375,36.825 69.375,35.856 75.481,29.75 86.194,29.75 90.135,33.691 90.135,35.043 89.738,35.44 89.582,35.44 89.364,35.658 89.364,37.233 88.882,37.715 U2.F2@88.86,37.715
DDR_DQ3_B: U1.E25 U2.U2 | length 29.8
  Top Layer w0.09: U1.E25@68.375,45.825 68.402,45.852 68.402,45.96 68.781,46.339 70.074,46.339 74.995,51.26 87.242,51.26 90.317,48.185 90.317,45.697 89.814,45.194 89.434,45.194 89.159,44.919 88.934,44.919 U2.U2@88.859,44.844
DDR_DQ4_A: U1.W25 U2.F4 | length 29.9
  Top Layer w0.09: U1.W25@68.374,38.826 68.623,39.075 70.717,39.075 72.632,37.16 73.793,37.16 74.916,36.037 74.916,35.923 74.835,35.842 74.699,35.842 74.088,36.454 73.97,36.454 73.882,36.366 73.882,36.249 74.58,35.551 75.401,35.551 78.342,32.61 79.496,32.61 79.557,32.55 82.962,32.55 83.022,32.61 83.838,32.61 84.956,33.728 85.488,33.728 85.578,33.818 85.578,33.949 85.251,34.276 85.251,34.598 85.548,34.895 85.548,35.03 85.309,35.269 85.309,35.744 85.409,35.844 85.409,35.988 85.309,36.088 85.309,36.579 85.409,36.679 85.409,36.791 85.129,37.071 85.129,37.261 85.267,37.399 86.546,37.399 86.783,37.162 86.93,37.162 87.255,37.487 U2.F4@87.255,37.71
DDR_DQ4_B: U1.J25 U2.U4 | length 28.2
  Top Layer w0.09: U1.J25@68.375,43.825 68.375,43.842 68.71,44.177 71.957,44.177 72.305,44.525 72.536,44.525 72.664,44.653 72.664,44.884 75.234,47.454 76.021,47.454 77.447,46.028 77.89,46.028 78.138,45.78 78.821,45.78 79.158,46.117 79.158,46.196 79.557,46.596 79.557,46.81 80.273,47.527 ; 80.274,47.527 80.274,47.693 80.564,47.982 80.564,48.222 80.742,48.4 80.978,48.4 81.135,48.243 81.385,48.243 81.542,48.4 81.778,48.4 81.946,48.233 82.174,48.233 82.342,48.4 82.578,48.4 82.713,48.266 83.007,48.266 83.142,48.4 83.378,48.4 83.524,48.254 83.796,48.254 83.942,48.4 84.767,48.4 84.86,48.307 84.86,47.879 84.656,47.674 84.656,47.525 84.737,47.445 85.004,47.445 85.076,47.373 85.076,47.105 85.724,46.457 85.724,46.142 85.897,45.969 86.184,45.969 86.281,45.871 86.281,45.761 86.197,45.677 85.962,45.677 85.854,45.569 85.854,45.362 85.968,45.247 86.183,45.247 86.258,45.172 86.258,45.067 86.121,44.929 85.936,44.929 85.854,44.847 85.854,44.724 85.948,44.63 86.237,44.63 86.339,44.528 87.147,44.528 87.261,44.641 U2.U4@87.26,44.865
DDR_DQ5_A: U1.W27 U2.E4 | length 29.1
  Top Layer w0.09: U1.W27@69.377,38.829 69.391,38.815 70.567,38.815 72.512,36.87 73.673,36.87 73.773,36.77 73.773,36.667 73.683,36.577 73.207,36.577 73.121,36.491 73.121,36.304 73.196,36.229 73.492,36.229 74.22,35.501 74.222,35.5 74.222,35.345 74.305,35.261 75.28,35.261 75.892,34.65 ; 75.892,34.65 76.055,34.488 76.055,34.351 75.765,34.061 75.765,33.956 75.864,33.857 75.972,33.857 76.263,34.148 76.394,34.148 77.891,32.651 77.891,32.428 77.999,32.32 83.959,32.32 85.076,33.438 85.83,33.438 86.109,33.718 86.109,33.842 85.654,34.297 85.654,34.591 86.003,34.94 86.003,35.041 85.599,35.445 85.599,35.624 85.722,35.747 85.722,36.085 85.599,36.208 85.599,36.457 85.759,36.617 86.055,36.617 86.218,36.78 86.544,36.78 86.791,36.533 86.893,36.533 87.065,36.705 87.645,36.705 87.728,36.787 87.728,36.944 87.646,37.025 87.3,37.025 U2.E4@87.26,37.065
DDR_DQ5_B: U1.H25 U2.V4 | length 27.7
  Top Layer w0.09: U1.H25@68.375,44.325 68.417,44.367 71.737,44.367 75.114,47.744 76.141,47.744 77.568,46.318 78.01,46.318 78.258,46.07 78.701,46.07 78.868,46.237 78.868,46.316 79.267,46.716 79.267,46.954 79.983,47.67 79.984,47.828 80.274,48.117 80.274,48.577 80.387,48.69 81.098,48.69 81.223,48.565 81.297,48.565 81.422,48.69 81.898,48.69 82.022,48.566 82.097,48.566 82.221,48.69 82.698,48.69 82.823,48.565 82.897,48.565 83.022,48.69 83.498,48.69 83.583,48.605 83.623,48.565 83.697,48.565 83.822,48.69 85,48.69 85.261,48.429 85.5,48.429 85.559,48.37 85.559,48.135 85.506,48.082 85.228,48.082 85.15,48.004 85.15,47.804 85.203,47.751 85.561,47.751 85.645,47.667 85.645,47.478 85.537,47.37 85.437,47.37 85.366,47.3 85.366,47.225 85.688,46.904 86.046,46.904 86.274,47.132 86.558,47.132 86.837,46.853 86.837,46.715 87.061,46.491 87.654,46.491 87.742,46.404 87.742,45.81 87.662,45.73 87.506,45.73 87.27,45.494 U2.V4@87.259,45.494
DDR_DQ6_A: U1.W26 U2.C4 | length 29.1
  Top Layer w0.09: U1.W26@68.875,38.825 69.125,38.575 69.479,38.575 69.529,38.625 70.347,38.625 72.392,36.58 72.738,36.58 72.831,36.487 72.831,36.141 73.032,35.939 73.372,35.939 73.897,35.415 73.897,35.054 73.979,34.971 75.16,34.971 75.652,34.479 75.652,34.359 75.366,34.072 75.366,33.946 75.863,33.448 75.973,33.448 76.271,33.746 76.386,33.746 77.601,32.531 77.601,32.389 77.532,32.319 77.402,32.319 76.38,33.341 76.276,33.341 76.18,33.245 76.18,33.13 77.28,32.03 84.079,32.03 85.196,33.148 85.952,33.148 86.441,33.637 ; U2.C4@87.26,35.765 87.037,35.542 86.835,35.542 86.745,35.452 86.745,35.345 86.836,35.254 86.836,35.088 86.605,34.857 86.605,34.723 86.747,34.581 86.747,34.448 86.745,34.446 86.745,34.347 86.44,34.042 86.44,33.638 ; 86.44,33.638 86.441,33.637
DDR_DQ6_B: U1.G26 U2.Y4 | length 25.9
  Top Layer w0.09: U1.G26@68.877,44.829 69.133,44.573 71.533,44.573 74.994,48.034 75.629,48.034 75.7,48.106 75.7,48.718 75.828,48.846 75.923,48.846 75.989,48.779 75.989,48.104 76.059,48.034 76.261,48.034 77.687,46.608 77.972,46.608 78.131,46.608 78.378,46.36 78.502,46.36 78.596,46.455 78.596,46.553 78.391,46.759 78.391,46.862 78.466,46.938 78.634,46.938 78.807,46.765 78.906,46.765 78.977,46.836 78.977,47.074 79.694,47.792 79.694,47.948 79.984,48.238 79.984,48.899 80.065,48.98 85.224,48.98 85.485,48.719 85.811,48.719 85.864,48.666 85.864,47.944 85.932,47.876 86.13,47.876 86.247,47.759 86.577,47.759 86.754,47.582 86.754,47.248 87.208,46.794 U2.Y4@87.259,46.794
DDR_DQ7_A: U1.Y25 U2.B4 | length 29.9
  Top Layer w0.09: U1.Y25@68.375,38.325 68.62,38.325 68.682,38.387 70.174,38.387 71.498,37.064 71.498,36.927 71.365,36.794 71.365,36.68 71.444,36.601 71.698,36.601 71.771,36.674 71.888,36.674 72.636,35.926 72.636,35.768 72.76,35.644 73.257,35.644 73.606,35.296 73.606,34.757 73.682,34.681 75.04,34.681 75.246,34.476 75.246,34.362 75.076,34.192 75.076,32.969 76.305,31.74 76.487,31.74 76.565,31.818 76.565,31.925 75.391,33.098 75.391,33.218 75.481,33.307 75.593,33.307 76.865,32.035 76.865,31.863 76.988,31.74 84.199,31.74 84.54,32.082 84.963,32.082 85.073,32.191 85.073,32.614 85.316,32.858 86.072,32.858 86.807,33.593 86.807,33.701 86.731,33.777 86.731,34.064 86.964,34.297 86.964,34.819 U2.B4@87.26,35.115
DDR_DQ7_B: U1.G25 U2.AA4 | length 28.3
  Top Layer w0.09: U1.G25@68.374,44.826 68.623,45.075 71.214,45.075 74.754,48.614 75.062,48.614 75.12,48.673 75.12,48.958 75.722,49.56 76.504,49.56 76.569,49.494 76.569,49.369 76.455,49.254 76.455,49.134 76.569,49.02 76.569,48.547 77.854,47.262 77.97,47.262 78.08,47.372 78.08,47.483 77.609,47.954 77.609,48.064 77.706,48.161 77.814,48.161 78.456,47.518 78.6,47.518 79.099,48.016 79.099,48.341 79.169,48.412 79.329,48.412 79.403,48.485 79.403,48.642 79.316,48.729 79.17,48.729 79.099,48.8 79.099,49.443 79.216,49.56 85.622,49.56 ; 85.623,49.56 85.69,49.493 85.69,49.367 85.758,49.299 85.914,49.299 85.98,49.365 85.98,49.497 86.043,49.56 86.21,49.56 86.276,49.494 86.276,49.18 86.964,48.492 86.964,47.972 87.259,47.677 U2.AA4@87.259,47.444
DDR_DQ8_A: U1.R27 U2.B11 | length 20.4
  Top Layer w0.09: U1.R27@69.378,40.828 72.189,40.828 73.576,39.44 75.832,39.44 75.945,39.327 75.945,38.257 76.14,38.062 77.697,38.062 77.975,38.34 77.975,39.352 78.063,39.44 78.177,39.44 78.265,39.352 78.265,38.163 77.976,37.874 77.976,37.541 78.258,37.259 78.258,37.23 78.265,37.223 78.265,35.912 79.028,35.149 79.287,34.89 80.187,34.89 80.285,34.988 80.285,35.141 80.36,35.215 80.498,35.215 80.575,35.138 80.575,34.826 80.65,34.751 80.987,34.751 81.183,34.555 81.332,34.555 81.659,34.882 U2.B11@81.66,35.115
DDR_DQ8_B: U1.J26 U2.AA11 | length 23.9
  Top Layer w0.09: U1.J26@68.875,43.825 68.879,43.829 68.915,43.829 69.065,43.979 72.169,43.979 72.425,44.235 72.874,44.235 72.954,44.314 72.954,44.764 73.065,44.875 73.172,44.875 73.243,44.804 73.243,44.315 73.324,44.235 73.454,44.235 73.536,44.316 73.536,44.977 73.449,45.063 73.449,45.259 74.749,46.559 74.863,46.559 75.035,46.387 75.157,46.387 75.235,46.465 75.235,46.605 75.074,46.767 75.074,46.884 75.354,47.164 75.901,47.164 76.198,46.867 76.198,46.72 76.106,46.628 76.106,46.499 76.182,46.423 76.642,46.423 77.239,45.827 77.239,45.535 77.328,45.446 77.425,45.446 77.529,45.55 77.529,45.662 77.605,45.738 77.77,45.738 77.886,45.622 77.886,45.497 77.73,45.342 77.73,43.53 77.8,43.46 77.952,43.46 78.02,43.528 78.02,45.22 78.29,45.49 78.658,45.49 78.748,45.399 78.851,45.399 79.448,45.997 79.448,46.076 79.903,46.531 ; 79.904,46.531 79.904,46.746 80.575,47.417 80.575,47.583 80.771,47.779 80.931,47.779 81.091,47.939 81.34,47.939 81.449,47.83 81.563,47.83 81.659,47.734 U2.AA11@81.66,47.465
DDR_DQ9_A: U1.R26 U2.C11 | length 21.2
  Top Layer w0.09: U1.R26@68.875,40.825 69.125,41.075 72.352,41.075 73.697,39.73 76.134,39.73 76.235,39.629 76.235,38.453 76.336,38.352 76.622,38.352 76.809,38.539 77.063,38.539 77.25,38.352 77.577,38.352 77.685,38.46 77.685,39.625 77.79,39.73 78.453,39.73 78.555,39.628 78.555,38.043 78.292,37.78 78.292,37.635 78.555,37.372 78.555,36.912 78.676,36.791 78.676,36.538 78.555,36.417 78.555,36.032 79.407,35.18 79.914,35.18 ; 79.915,35.181 80.279,35.545 80.578,35.545 80.674,35.449 80.929,35.449 81.182,35.196 81.29,35.196 81.367,35.274 81.367,35.691 81.436,35.759 81.654,35.759 U2.C11@81.66,35.765
DDR_DQ9_B: U1.K25 U2.Y11 | length 23.9
  Top Layer w0.09: U1.K25@68.375,43.325 68.625,43.575 68.984,43.575 69.183,43.774 72.374,43.774 72.545,43.945 74.245,43.945 74.323,44.023 74.323,44.15 74.236,44.237 73.921,44.237 73.826,44.333 73.826,45.226 74.697,46.097 75.451,46.097 75.525,46.172 75.525,46.802 75.598,46.874 75.74,46.874 75.816,46.799 75.816,46.203 75.886,46.133 76.522,46.133 76.949,45.706 76.949,45.225 77.018,45.156 77.361,45.156 77.44,45.077 77.44,43.24 77.51,43.17 78.237,43.17 78.31,43.243 78.31,45.1 78.41,45.2 78.537,45.2 78.629,45.108 78.629,44.919 78.706,44.842 78.874,44.842 78.954,44.923 78.954,45.093 79.515,45.654 79.655,45.654 ; 79.656,45.654 79.765,45.763 79.765,45.982 79.769,45.982 80.194,46.407 80.194,46.626 80.403,46.835 80.477,46.835 80.783,47.142 81.038,47.142 81.196,47.3 81.327,47.3 81.447,47.18 81.577,47.18 81.659,47.097 U2.Y11@81.66,46.815
DDR_DQ10_A: U1.P27 U2.E11 | length 20.4
  Top Layer w0.09: U1.P27@69.377,41.329 69.401,41.305 72.532,41.305 73.817,40.02 76.417,40.02 76.525,39.912 76.525,38.936 76.632,38.829 77.276,38.829 77.395,38.948 77.395,39.902 77.513,40.02 78.731,40.02 78.845,39.906 78.845,37.032 79.049,36.828 79.049,36.501 78.845,36.297 78.845,36.152 79.527,35.47 79.795,35.47 80.08,35.755 80.08,36.576 80.171,36.667 80.608,36.667 80.69,36.749 81.006,36.749 81.1,36.655 81.304,36.655 81.66,37.01 U2.E11@81.66,37.065
DDR_DQ10_B: U1.K26 U2.V11 | length 23.8
  Top Layer w0.09: U1.K26@68.875,43.325 68.898,43.35 69.03,43.35 69.257,43.578 72.588,43.578 72.665,43.655 74.226,43.655 74.426,43.456 74.544,43.456 74.613,43.525 74.613,44.465 74.55,44.527 74.217,44.527 74.116,44.629 74.116,45.105 74.809,45.799 75.413,45.799 75.484,45.728 75.484,44.878 75.536,44.825 75.722,44.825 75.775,44.878 75.775,45.768 75.85,45.843 76.402,45.843 76.659,45.586 76.659,44.906 76.729,44.836 77.082,44.836 77.15,44.768 77.15,42.954 77.224,42.88 78.527,42.88 78.6,42.953 78.6,43.859 78.782,44.041 78.782,44.151 78.6,44.333 78.6,44.461 78.691,44.552 78.848,44.552 79.015,44.385 79.126,44.385 79.253,44.512 79.253,44.982 79.635,45.364 79.776,45.364 80.055,45.643 80.055,45.862 80.257,46.064 80.543,46.064 80.798,45.809 81.011,45.809 81.231,46.029 81.379,46.029 81.62,45.788 81.62,45.554 U2.V11@81.66,45.515
DDR_DQ11_A: U1.P26 U2.F11 | length 20.8
  Top Layer w0.09: U1.P26@68.875,41.325 68.889,41.339 69.035,41.339 69.271,41.575 69.638,41.575 69.658,41.555 72.692,41.555 73.937,40.31 76.699,40.31 76.815,40.194 76.815,39.398 76.897,39.316 77.031,39.316 77.105,39.39 77.105,40.203 77.212,40.31 79.002,40.31 79.135,40.177 79.135,37.152 79.342,36.945 79.342,36.066 79.439,35.968 79.583,35.968 79.779,36.165 79.779,36.816 80.002,37.04 80.002,37.417 80.155,37.569 80.502,37.569 80.697,37.374 81.331,37.374 U2.F11@81.666,37.709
